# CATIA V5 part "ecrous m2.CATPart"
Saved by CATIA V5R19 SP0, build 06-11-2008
Part number: ecrous m.2
Bounding box of the stored display mesh (mm): x 0 to 1.2, y -1.877 to 1.877, z -2.16 to 2.16
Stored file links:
  G:\project guitar elect\ecrous m2.CATPart
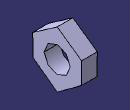
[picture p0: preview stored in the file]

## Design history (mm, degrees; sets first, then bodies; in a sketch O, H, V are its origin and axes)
Body1 (main body)
  Sketch1 on yz-plane, origin (0, 0, 0), H (0, 1, 0), V (0, 0, 1)
    point P1 (1.876, -0.7805)
    line L1 (1.876, -0.7805) -> (1.8774, 0.8512)
    point P2 (1.8774, 0.8512)
    line L2 (1.8774, 0.8512) -> (0, 2.16)
    point P3 (0, 2.16)
    line L3 (1.876, -0.7805) -> (0, -2.16)
    point P4 (0, -2.16)
    axis line L4 (0, 2.16) -> (0, -2.16)
    point P5 (0, 2.16)
    point P7 (0, -2.16)
    point P8 (-1.876, -0.7805)
    line L5 (-1.876, -0.7805) -> (0, -2.16)
    point P9 (-1.8774, 0.8512)
    line L6 (-1.876, -0.7805) -> (-1.8774, 0.8512)
    point P10 (0, 2.16)
    line L7 (-1.8774, 0.8512) -> (0, 2.16)
    coincidence: P3 V, P4 V, P5 L2, P3 P10, P4 P7
    vertical: L4 V
    symmetry: P4 P7 L4, P1 P8 L4, L3 L5 L4, P2 P9 L4, L1 L6 L4, P3 P10 L4, L2 L7 L4
  Pad1: profile Sketch1, direction (1, 0, 0), length 1.2
  Sketch2 on end face of Pad1, origin (1.2, 0, 0), H (0, 1, 0), V (0, 0, 1)
    circle A1 centre (0, 0) radius 1
    radius A1 = 1
  Pocket1: profile Sketch2, direction (-1, 0, 0), length 1.2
